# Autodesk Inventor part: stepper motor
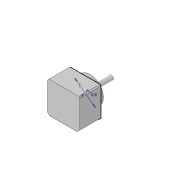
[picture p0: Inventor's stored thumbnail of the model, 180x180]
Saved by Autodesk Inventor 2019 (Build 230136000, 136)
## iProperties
Created: 2019-10
Part Number: stepper motor
Material: Generic
Document SubType Name: Modeling
Designer: Hp
Density: 1 g/cm^3
Appearance: Default
Author: Hp
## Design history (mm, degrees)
sketch "Sketch1"
  geometry: L1 (-3.089, 2.5)-(-3.089, -2.739); L2 (-2.832, 2.821)-(2.844, 2.821); L3 (3.007, 2.582)-(3.007, -2.656); L4 (-2.718, -3.151)-(2.5, -3.151); L5 (2.844, 2.821)-(3.007, 2.582); L6 (2.5, -3.151)-(3.007, -2.656); L7 (-3.089, 2.5)-(-2.832, 2.821); L8 (-3.089, -2.739)-(-2.718, -3.151); C1 r 2.5 at (0, 0); C2 r 0.4 at (0, 0); 1 further point
  constraints: 16 end point, 2 centre point, 2 coincident, 2 horizontal, 2 vertical
  dimensions: "d3" = 5 diameter of C1; "d27" = 0.8 diameter of C2
extrude "Extrusion1" new body sketch "Sketch1" distance "d1" = 4; taper "d2" = 0 deg
extrude "Extrusion2" join sketch "Sketch1" distance "d4" = 1; taper "d5" = 0 deg
sketch "Sketch2"
  geometry: 2 further points
hole "Hole1" sketch "Sketch2" at (-0.023, -0.029) diameter "d6" = 1; stored, may be unused: countersink angle "d10" = 82 deg, drill point angle "d12" = 118 deg; dims "d7" = 2.002, "d8" = 19.05, "d9" = 4.775, "d11" = 3
sketch "Sketch3"
  geometry: 2 further points
  constraints: 1 coincident
hole "Hole2" sketch "Sketch3" at (0, 0) diameter "d13" = 1; stored, may be unused: countersink angle "d17" = 82 deg, drill point angle "d19" = 0 deg; dims "d14" = 2.002, "d15" = 19.05, "d16" = 4.775, "d18" = 12
sketch "Sketch4"
  geometry: 2 further points
  constraints: 1 coincident
hole "Hole3" sketch "Sketch4" at (0, 0) diameter "d20" = 1; stored, may be unused: countersink angle "d24" = 82 deg, drill point angle "d26" = 0 deg; dims "d21" = 2.002, "d22" = 19.05, "d23" = 4.775, "d25" = 12
extrude "Extrusion3" join sketch "Sketch1" distance "d28" = 5; taper "d29" = 0 deg
body "Solid1"
